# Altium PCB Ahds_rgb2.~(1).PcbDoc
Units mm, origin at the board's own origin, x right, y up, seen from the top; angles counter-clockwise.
Board outline 55.52 x 97.28 mm, 2 copper layers (Top Layer, Bottom Layer); 73 components, 40 nets, 226 pads, 1 vias.
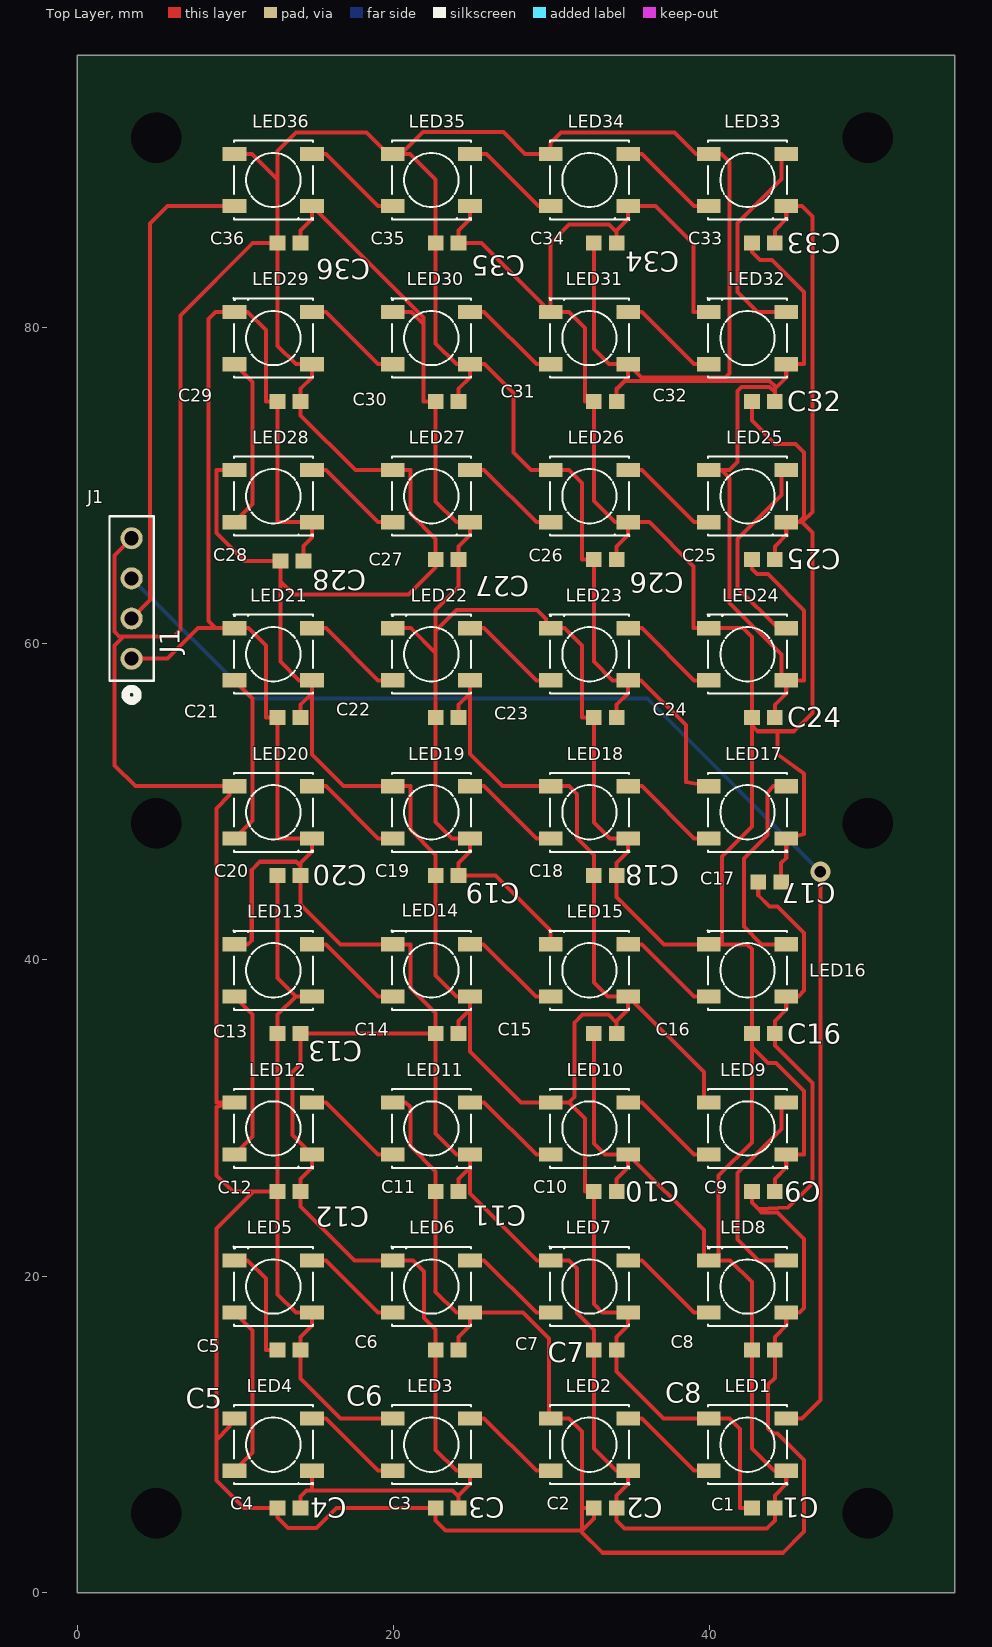
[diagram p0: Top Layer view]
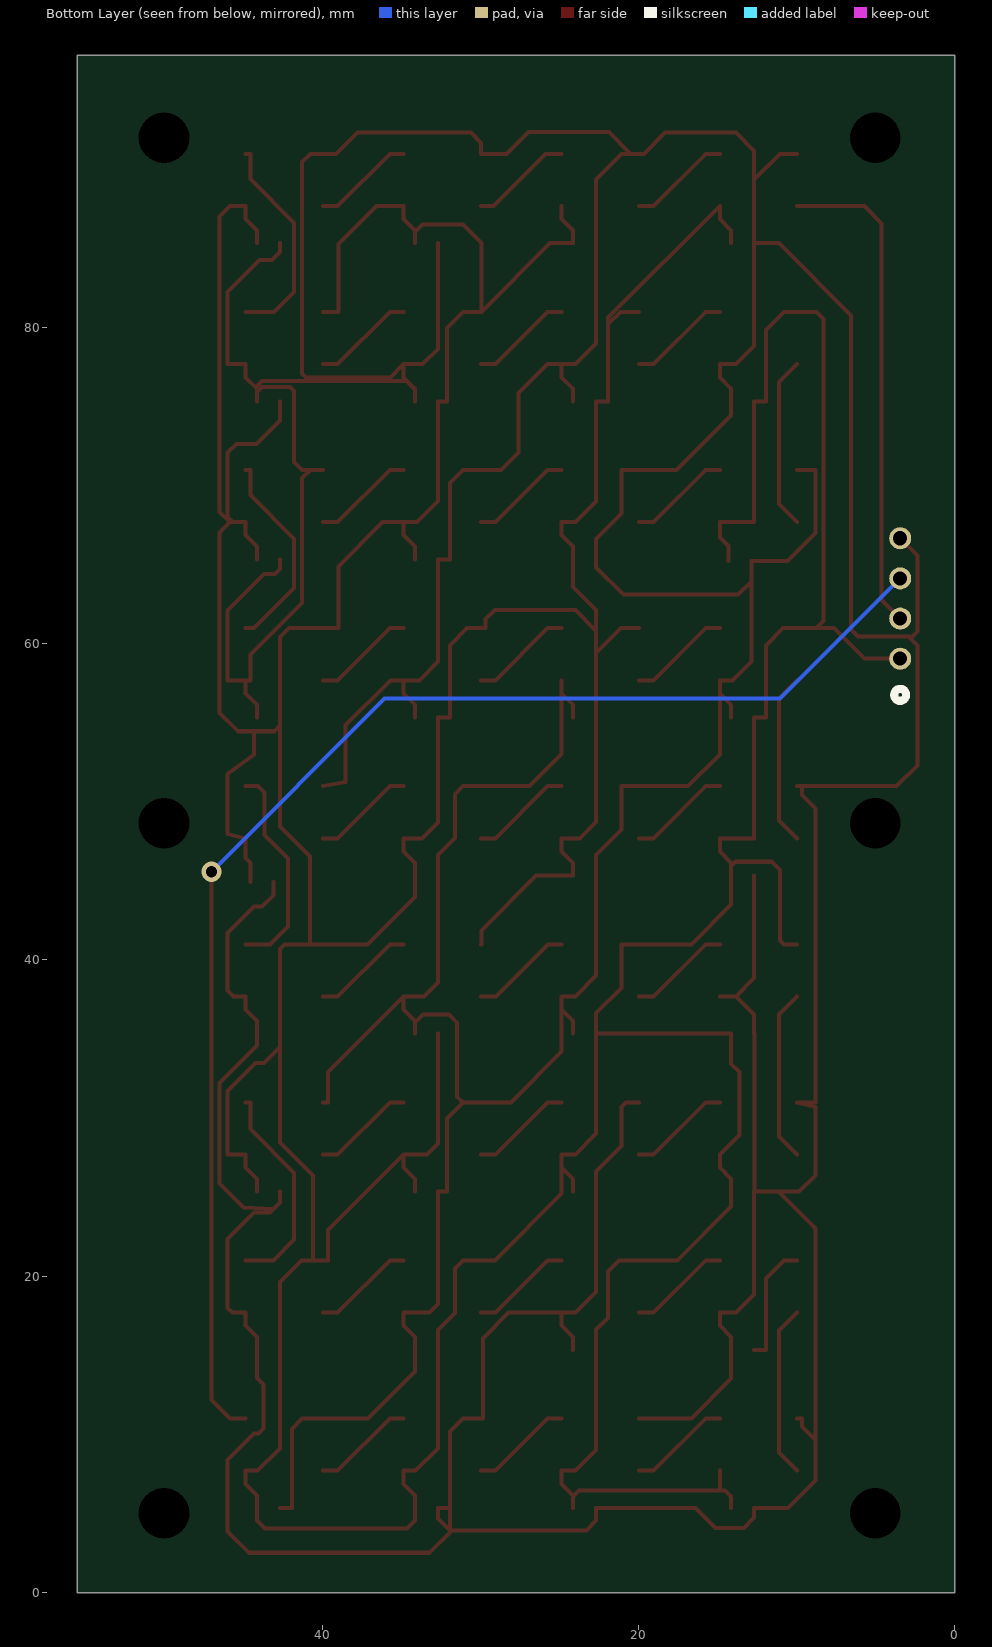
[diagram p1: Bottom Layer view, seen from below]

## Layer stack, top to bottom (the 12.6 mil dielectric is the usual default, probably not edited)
Top Solder: solder mask 0.0102, Solder Resist, Dk 3.5
Top Layer: signal copper 0.0356
Dielectric 1: dielectric 0.32, FR-4, Dk 4.8
Bottom Layer: signal copper 0.0356
Bottom Solder: solder mask 0.0102, Solder Resist, Dk 3.5

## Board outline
-0.018,-0.042 55.499,-0.042 55.499,97.24 -0.018,97.24

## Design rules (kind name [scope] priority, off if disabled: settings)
Clearance [All] p1: gap=0.254 ignorepadtopadclearanceinfootprint=TRUE
HoleSize [All] p1: absolutevalues=TRUE maxlimit=3.5 minlimit=0.025 maxpercent=80.000 minpercent=20.000
PolygonConnect [All] p1: connectstyle=Relief reliefconductorwidth=0.254 reliefentries=4 polygonreliefangle="90 Angle" airgapwidth=0.254
RoutingVias [All] p1: holewidth=0.711 width=1.27 viastyle="Through Hole" minholewidth=0.711 minwidth=1.27 maxholewidth=0.711 maxwidth=1.27
SolderMaskExpansion [All] p1: expansion=0.102 istentingtop=FALSE
Width [All] p1: maxlimit=0.254 minlimit=0.254 preferedwidth=0.254
29 further rules are at their usual default settings.

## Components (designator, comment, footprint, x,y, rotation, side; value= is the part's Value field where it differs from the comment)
C1 "100nF" CAPC17595_87N_KEM 43.393,5.339 r180 top
C2 "100nF" CAPC17595_87N_KEM 33.393,5.339 r180 top
C3 "100nF" CAPC17595_87N_KEM 23.393,5.339 r180 top
C4 "100nF" CAPC17595_87N_KEM 13.393,5.339 r180 top
C5 "100nF" CAPC17595_87N_KEM 13.393,15.339 r0 top
C6 "100nF" CAPC17595_87N_KEM 23.393,15.339 r0 top
C7 "100nF" CAPC17595_87N_KEM 33.393,15.339 r0 top
C8 "100nF" CAPC17595_87N_KEM 43.393,15.339 r0 top
C9 "100nF" CAPC17595_87N_KEM 43.393,25.339 r180 top
C10 "100nF" CAPC17595_87N_KEM 33.393,25.339 r180 top
C11 "100nF" CAPC17595_87N_KEM 23.393,25.339 r180 top
C12 "100nF" CAPC17595_87N_KEM 13.393,25.339 r180 top
C13 "100nF" CAPC17595_87N_KEM 13.393,35.339 r180 top
C14 "100nF" CAPC17595_87N_KEM 23.393,35.339 r0 top
C15 "100nF" CAPC17595_87N_KEM 33.393,35.339 r0 top
C16 "100nF" CAPC17595_87N_KEM 43.393,35.339 r0 top
C17 "100nF" CAPC17595_87N_KEM 43.797,44.916 r180 top
C18 "100nF" CAPC17595_87N_KEM 33.393,45.339 r180 top
C19 "100nF" CAPC17595_87N_KEM 23.393,45.339 r180 top
C20 "100nF" CAPC17595_87N_KEM 13.393,45.339 r180 top
C21 "100nF" CAPC17595_87N_KEM 13.393,55.339 r0 top
C22 "100nF" CAPC17595_87N_KEM 23.393,55.339 r0 top
C23 "100nF" CAPC17595_87N_KEM 33.393,55.339 r0 top
C24 "100nF" CAPC17595_87N_KEM 43.393,55.339 r0 top
C25 "100nF" CAPC17595_87N_KEM 43.393,65.339 r180 top
C26 "100nF" CAPC17595_87N_KEM 33.393,65.339 r180 top
C27 "100nF" CAPC17595_87N_KEM 23.393,65.339 r180 top
C28 "100nF" CAPC17595_87N_KEM 13.571,65.236 r180 top
C29 "100nF" CAPC17595_87N_KEM 13.393,75.339 r0 top
C30 "100nF" CAPC17595_87N_KEM 23.393,75.339 r0 top
C31 "100nF" CAPC17595_87N_KEM 33.393,75.339 r0 top
C32 "100nF" CAPC17595_87N_KEM 43.393,75.339 r0 top
C33 "100nF" CAPC17595_87N_KEM 43.393,85.339 r180 top
C34 "100nF" CAPC17595_87N_KEM 33.393,85.339 r180 top
C35 "100nF" CAPC17595_87N_KEM 23.393,85.339 r180 top
C36 "100nF" CAPC17595_87N_KEM 13.393,85.339 r180 top
J1 "901471304" CONN04_901471304_MOL 3.429,59.055 r90 top
LED1 "WS2812B" *WS2812B_WS2812B(Primary) 42.393,9.339 r0 top
LED2 "WS2812B" *WS2812B_WS2812B(Primary) 32.393,9.339 r0 top
LED3 "WS2812B" *WS2812B_WS2812B(Primary) 22.393,9.339 r0 top
LED4 "WS2812B" *WS2812B_WS2812B(Primary) 12.393,9.339 r0 top
LED5 "WS2812B" *WS2812B_WS2812B(Primary) 12.393,19.339 r180 top
LED6 "WS2812B" *WS2812B_WS2812B(Primary) 22.393,19.339 r180 top
LED7 "WS2812B" *WS2812B_WS2812B(Primary) 32.393,19.339 r180 top
LED8 "WS2812B" *WS2812B_WS2812B(Primary) 42.393,19.339 r180 top
LED9 "WS2812B" *WS2812B_WS2812B(Primary) 42.393,29.339 r0 top
LED10 "WS2812B" *WS2812B_WS2812B(Primary) 32.393,29.339 r0 top
LED11 "WS2812B" *WS2812B_WS2812B(Primary) 22.393,29.339 r0 top
LED12 "WS2812B" *WS2812B_WS2812B(Primary) 12.393,29.339 r0 top
LED13 "WS2812B" *WS2812B_WS2812B(Primary) 12.393,39.339 r180 top
LED14 "WS2812B" *WS2812B_WS2812B(Primary) 22.393,39.339 r180 top
LED15 "WS2812B" *WS2812B_WS2812B(Primary) 32.393,39.339 r180 top
LED16 "WS2812B" *WS2812B_WS2812B(Primary) 42.393,39.339 r180 top
LED17 "WS2812B" *WS2812B_WS2812B(Primary) 42.393,49.339 r0 top
LED18 "WS2812B" *WS2812B_WS2812B(Primary) 32.393,49.339 r0 top
LED19 "WS2812B" *WS2812B_WS2812B(Primary) 22.393,49.339 r0 top
LED20 "WS2812B" *WS2812B_WS2812B(Primary) 12.393,49.339 r0 top
LED21 "WS2812B" *WS2812B_WS2812B(Primary) 12.393,59.339 r180 top
LED22 "WS2812B" *WS2812B_WS2812B(Primary) 22.393,59.339 r180 top
LED23 "WS2812B" *WS2812B_WS2812B(Primary) 32.393,59.339 r180 top
LED24 "WS2812B" *WS2812B_WS2812B(Primary) 42.393,59.339 r180 top
LED25 "WS2812B" *WS2812B_WS2812B(Primary) 42.393,69.339 r0 top
LED26 "WS2812B" *WS2812B_WS2812B(Primary) 32.393,69.339 r0 top
LED27 "WS2812B" *WS2812B_WS2812B(Primary) 22.393,69.339 r0 top
LED28 "WS2812B" *WS2812B_WS2812B(Primary) 12.393,69.339 r0 top
LED29 "WS2812B" *WS2812B_WS2812B(Primary) 12.393,79.339 r180 top
LED30 "WS2812B" *WS2812B_WS2812B(Primary) 22.393,79.339 r180 top
LED31 "WS2812B" *WS2812B_WS2812B(Primary) 32.393,79.339 r180 top
LED32 "WS2812B" *WS2812B_WS2812B(Primary) 42.393,79.339 r180 top
LED33 "WS2812B" *WS2812B_WS2812B(Primary) 42.393,89.339 r0 top
LED34 "WS2812B" *WS2812B_WS2812B(Primary) 32.393,89.339 r0 top
LED35 "WS2812B" *WS2812B_WS2812B(Primary) 22.393,89.339 r0 top
LED36 "WS2812B" *WS2812B_WS2812B(Primary) 12.393,89.339 r0 top

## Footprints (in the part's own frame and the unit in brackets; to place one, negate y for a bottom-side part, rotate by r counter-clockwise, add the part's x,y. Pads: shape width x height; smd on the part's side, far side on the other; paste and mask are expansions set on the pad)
*WS2812B_WS2812B(Primary) [mm]
  rect 1.5x0.9 smd: 1(2.45,-1.65) 2(2.45,1.65) 3(-2.45,1.65) 4(-2.45,-1.65)
  silkscreen extent -2.5,-2.52 2.52,2.5
CAPC17595_87N_KEM [mm]
  rect 1x0.95 smd paste+0 mask+0: 1(-0.725,0) 2(0.725,0)
  body extent -0.87,-0.48 0.87,0.48, height 0.87
CONN04_901471304_MOL [mil]
  round 55 hole 35 paste-99999 mask+0: 1(0,0) 2(100,0) 3(200,0) 4(300,0)
  silkscreen extent -105,-55 355,55

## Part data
C1 C2 C3 C4 C5 C6 C7 C8 C9 C10 C11 C12 C13 C14 C15 C16 C17 C18 C19 C20 C21 C22 C23 C24 C25 C26 C27 C28 C29 C30 C31 C32 C33 C34 C35 C36: library part C0603C103K4RECTU, "ESD SMD Comm X7R, Ceramic, 0.01 uF, 10%, 16 VDC, X7R, SMD, MLCC, Temperature Stable, Electro Static Discharge, Class II, 0603", Manufacturer_Name=Kemet
J1: "C-Grid III PCB Receptacle, 2.54mm Pitch, Single Row, Vertical, Shrouded, 4 Circuits, 0.76Âµm Gold (Au) Plating", Manufacturer_Name=Molex
LED1 LED2 LED3 LED4 LED5 LED6 LED7 LED8 LED9 LED10 LED11 LED12 LED13 LED14 LED15 LED16 LED17 LED18 LED19 LED20 LED21 LED22 LED23 LED24 LED25 LED26 LED27 LED28 LED29 LED30 LED31 LED32 LED33 LED34 LED35 LED36: "Intelligent control LED integrated light source", Package=None

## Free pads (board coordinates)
  round 1.524 hole 3.2: 1(5,5) 2(50,5) 3(50,48.64) 4(50,92) 5(5,92) 6(5,48.64)

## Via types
v1: diameter 1.27, hole 0.711, Top Layer to Bottom Layer, 1 vias

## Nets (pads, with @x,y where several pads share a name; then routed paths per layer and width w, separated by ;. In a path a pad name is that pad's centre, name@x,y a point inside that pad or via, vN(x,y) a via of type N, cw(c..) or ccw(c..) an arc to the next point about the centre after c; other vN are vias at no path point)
5V: C1.1 C2.1 C3.1 C4.1 C6.1 C7.1 C8.1 C9.1 C10.1 C11.1 C12.1 C13.1 C14.1 C15.1 C16.1 C17.1 C18.1 C19.1 C20.1 C21.1 C22.1 C23.1 C24.1 C25.1 C26.1 C27.1 C28.1 C29.1 C30.1 C31.1 C32.1 C33.1 C34.1 C35.1 C36.1 J1.1 LED1.1 LED2.1 LED3.1 LED4.1 LED6.1 LED7.1 LED8.1 LED9.1 LED10.1 LED11.1 LED12.1 LED13.1 LED14.1 LED15.1 LED16.1 LED17.1 LED18.1 LED19.1 LED20.1 LED21.1 LED22.1 LED23.1 LED24.1 LED25.1 LED26.1 LED27.1 LED28.1 LED29.1 LED30.1 LED31.1 LED32.1 LED33.1 LED34.1 LED35.1 LED36.1 | length 535.7
  Top Layer w0.254: J1.1 5.697,59.055 7.631,60.989 8.725,60.989 ; LED13.1 10.777,40.989 11.031,41.243 11.031,45.678 11.565,46.212 13.839,46.212 14.118,45.932 ; C4.1@14.118,5.339 14.118,6.054 14.499,6.435 14.843,6.435 ; C36.1 14.118,86.14 14.843,86.865 LED36.1 21.902,80.63 21.902,80.222 ; C28.1 14.296,66.176 14.843,66.723 LED28.1 12.708,67.689 12.668,67.729 C29.1 11.92,75.339 11.92,79.846 10.777,80.989 LED29.1 8.725,80.989 8.288,80.552 8.288,61.426 8.725,60.989 ; LED4.1 14.843,6.435 ; LED22.1 21.09,60.989 22.668,59.411 ; LED30.1 21.135,80.989 21.902,80.222 ; C3.1@24.118,5.339 24.118,6.054 ; C11.1 24.118,26.146 24.843,26.871 ; LED35.1 24.843,86.865 24.118,86.14 C35.1 25.579,85.339 LED31.1@29.929,80.989 ; LED15.1 29.929,40.989 29.929,41.868 26.458,45.339 C19.1 24.118,46.135 24.843,46.86 LED19.1 23.701,47.689 22.668,48.722 22.668,55.339 22.668,59.411 ; C15.1@32.668,35.339 32.668,28.385 33.364,27.689 LED10.1 ; C10.1 34.118,26.146 34.843,26.871 LED10.1 ; C26.1 34.118,66.151 34.843,66.876 LED26.1 ; C34.1 34.118,86.04 ; LED32.1 38.971,80.989 38.971,85.277 36.559,87.689 LED34.1 34.843,86.865 34.118,86.14 34.118,86.04 ; C32.1 42.668,74.126 44.141,72.653 45.423,72.653 45.982,72.094 45.982,68.03 45.641,67.689 ; C9.1 44.118,26.146 44.843,26.871 LED9.1 45.982,27.689 45.982,31.708 44.204,33.486 43.684,33.486 42.668,34.502 ; C25.1 44.118,66.151 44.843,66.876 LED25.1 45.641,67.689 ; C33.1 44.118,86.14 44.843,86.865 LED33.1 45.829,87.689 46.49,87.029 46.49,68.35 45.829,67.689 ; C17.1 44.522,46.135 44.843,46.456 LED17.1 45.982,47.964 45.982,51.774 44.305,52.993 44.305,54.467 ; 8.725,60.989 LED21.1 10.833,60.989 11.92,59.902 11.92,55.339 C21.1 12.668,47.703 12.682,47.689 LED20.1 14.843,46.86 14.118,46.135 14.118,45.932 ; 14.118,45.932 C20.1 14.118,43.516 16.645,40.989 LED14.1 21.064,40.989 21.064,38.24 22.668,36.636 C14.1@22.668,35.339 ; 14.843,6.435 23.737,6.435 24.118,6.054 ; 21.902,80.222 21.902,75.339 22.668,75.339 22.668,69.006 23.985,67.689 LED27.1 24.843,66.876 24.118,66.151 C27.1 24.118,63.587 22.668,62.137 22.668,60.82 ; C14.1@22.668,35.339 22.668,29.006 23.985,27.689 LED11.1 24.843,26.871 ; C14.1@22.668,35.339 C13.1 14.118,33.424 13.597,32.902 13.597,28.936 LED12.1 14.843,26.871 14.118,26.146 C12.1 14.118,24.405 17.534,20.989 LED6.1 21.217,20.989 21.928,20.278 21.928,17.361 22.668,16.621 22.668,15.339 22.668,9.006 23.985,7.689 LED3.1 24.843,6.855 24.118,6.13 24.118,6.054 ; 22.668,59.411 22.668,60.82 ; 22.668,60.82 23.985,62.137 29.065,62.137 29.649,61.553 29.649,60.989 LED23.1 30.823,60.989 31.91,59.902 31.91,55.339 32.668,55.339 32.668,48.705 33.684,47.689 LED18.1 34.843,46.86 34.118,46.135 C18.1 34.118,43.988 37.117,40.989 LED16.1 40.775,40.989 ; 24.843,26.871 24.843,25.211 29.065,20.989 LED7.1 31.097,20.989 31.605,20.481 31.605,17.658 32.668,16.595 32.668,15.339 32.668,9.102 34.081,7.689 LED2.1 34.843,6.855 34.118,6.13 34.118,5.339 34.118,4.53 34.626,4.022 43.61,4.022 44.118,4.53 44.118,5.339 44.118,6.13 44.843,6.855 LED1.1 44.081,7.689 42.668,9.102 C8.1 42.668,19.618 41.297,20.989 LED8.1@40.571,20.989 ; LED31.1@29.929,80.989 29.929,85.353 31.097,86.521 33.637,86.521 34.118,86.04 ; LED31.1@29.929,80.989 LED31.1 31.097,80.989 32.113,79.973 32.113,75.339 32.668,75.339 32.668,69.025 34.004,67.689 LED26.1 ; LED10.1 39.632,22.901 39.632,20.989 LED8.1 LED8.1@40.571,20.989 ; LED26.1 36.177,67.689 38.971,64.895 38.971,60.989 LED24.1 42.095,60.989 42.668,60.416 C24.1 42.668,54.822 ; LED8.1@40.571,20.989 40.571,26.349 42.668,28.446 42.668,34.502 ; 40.775,40.989 42.375,40.989 42.668,40.696 C16.1 42.668,34.502 ; 40.775,40.989 40.775,46.542 42.668,48.435 42.668,54.822 ; 42.668,54.822 43.024,54.467 44.305,54.467 ; 44.305,54.467 45.321,54.467 46.49,55.635 46.49,67.029 45.829,67.689 ; 45.641,67.689 45.829,67.689
GND: C1.2 C2.2 C3.2 C4.2 C5.2 C6.2 C7.2 C8.2 C9.2 C10.2 C11.2 C12.2 C13.2 C14.2 C15.2 C16.2 C17.2 C18.2 C19.2 C20.2 C21.2 C22.2 C23.2 C24.2 C25.2 C26.2 C27.2 C28.2 C29.2 C30.2 C31.2 C32.2 C33.2 C34.2 C35.2 C36.2 J1.4 LED1.3 LED2.3 LED3.3 LED4.3 LED5.3 LED6.3 LED7.3 LED8.3 LED9.3 LED10.3 LED11.3 LED12.3 LED13.3 LED14.3 LED15.3 LED16.3 LED17.3 LED18.3 LED19.3 LED20.3 LED21.3 LED22.3 LED23.3 LED24.3 LED25.3 LED26.3 LED27.3 LED28.3 LED29.3 LED30.3 LED31.3 LED32.3 LED33.3 LED34.3 LED35.3 LED36.3 | length 662.7
  Top Layer w0.254: J1.4 2.344,65.59 2.344,60.766 2.649,60.461 2.903,60.461 ; LED4.3 9.634,10.989 9.634,10.474 8.796,9.636 ; LED20.3 LED20.3@9.634,50.989 ; LED28.3 8.796,70.989 8.796,67.014 10.574,65.236 C28.2 12.846,63.955 ; LED36.3 11.045,90.989 12.668,89.366 ; C20.2 12.668,38.846 13.825,37.689 ; C21.2 14.118,56.143 14.843,56.868 ; LED13.3 13.825,37.689 ; LED3.3 16.645,10.989 14.118,13.516 C5.2 14.118,16.138 14.843,16.863 LED5.3 13.825,17.689 12.668,18.846 C12.2 C12.2@12.657,25.339 ; LED11.3 20.767,30.989 21.064,30.692 21.064,28.232 22.668,26.628 22.668,25.339 22.668,19.006 23.985,17.689 LED6.3 ; C6.2 24.118,16.138 24.843,16.863 LED6.3 ; C14.2 24.118,36.128 24.843,36.864 ; C22.2 24.118,56.143 24.843,56.868 ; C30.2 24.118,76.133 24.843,76.858 LED30.3 ; LED22.3 24.843,56.868 ; C34.2@32.668,85.339 32.668,78.658 33.637,77.689 LED31.3 ; C15.2 34.118,36.026 ; C23.2 34.118,56.143 34.843,56.868 LED23.3 ; C31.2 34.118,76.08 ; LED9.3 39.632,30.989 39.632,32.901 LED15.3 ; LED17.3 38.512,51.266 38.512,54.847 35.669,57.689 LED23.3 ; LED25.3 40.749,70.989 ; C1.2@42.668,5.339 41.918,5.339 41.918,10.329 41.257,10.989 LED1.3 37.092,10.989 34.118,13.963 C7.2 34.118,16.138 34.843,16.863 LED7.3 33.204,17.689 32.668,18.225 32.668,25.339 32.113,25.339 32.113,29.973 31.097,30.989 ; C9.2 42.668,24.658 43.08,24.246 ; C25.2 42.668,64.728 42.987,64.409 43.684,64.409 45.982,62.112 45.982,57.689 LED24.3 ; C33.2 42.668,84.794 43.176,84.286 43.95,84.286 45.982,82.254 45.982,77.689 LED32.3 44.843,76.858 44.118,76.133 ; C17.2 43.072,44.092 43.797,43.367 44.305,43.367 45.982,41.69 45.982,38.058 45.613,37.689 LED16.3 44.843,36.853 44.118,36.128 C16.2 44.118,34.588 46.49,32.216 46.49,25.866 44.966,24.342 43.08,24.246 ; C24.2 44.118,56.143 44.843,56.868 LED24.3 ; C32.2 44.118,75.913 ; 2.903,60.461 6.104,60.461 6.535,60.893 6.535,80.781 11.094,85.339 C36.2 ; 2.903,60.461 2.344,59.902 2.344,52.31 3.665,50.989 LED20.3@9.634,50.989 ; 8.796,9.636 8.796,22.996 11.139,25.339 ; 8.796,9.636 8.796,7.07 10.527,5.339 12.668,5.339 12.668,4.722 13.317,4.073 15.121,4.073 16.387,5.339 22.668,5.339 22.668,4.53 23.278,3.921 31.91,3.921 ; LED20.3@9.634,50.989 9.634,50.428 8.796,49.59 8.796,30.989 LED12.3 8.796,30.692 8.796,26.374 9.831,25.339 11.139,25.339 ; 11.139,25.339 C12.2@12.657,25.339 ; C12.2@12.657,25.339 12.657,35.339 C13.2 12.668,36.534 13.825,37.689 ; C36.2 12.668,89.366 ; C36.2 12.668,78.846 13.825,77.689 LED29.3 14.843,76.858 14.118,76.133 C29.2 14.118,74.455 17.584,70.989 LED27.3 21.064,70.989 21.064,68.237 22.668,66.633 22.668,65.339 22.668,64.834 20.937,63.103 13.698,63.103 12.846,63.955 ; 12.668,89.366 12.668,91.181 13.825,92.338 18.293,92.338 19.642,90.989 LED35.3 LED35.3@20.477,90.989 ; 12.846,63.955 12.846,58.875 14.032,57.689 LED21.3 14.843,56.868 ; 14.843,56.868 14.843,52.994 16.848,50.989 LED19.3 21.064,50.989 21.064,48.247 22.668,46.643 22.668,45.339 22.668,39.006 23.985,37.689 LED14.3 24.843,36.864 ; LED35.3@20.477,90.989 21.045,90.989 22.668,89.366 22.668,85.339 22.668,79.006 23.985,77.689 LED30.3 ; LED35.3@20.477,90.989 21.852,92.363 26.954,92.363 28.329,90.989 LED34.3 29.943,91.692 30.589,92.338 37.775,92.338 39.124,90.989 LED33.3 40.749,90.989 41.257,90.481 41.257,77.098 41.003,76.844 35.688,76.844 LED31.3 ; LED6.3 28.202,17.689 29.827,16.064 29.827,10.989 LED2.3 31.097,10.989 31.91,10.176 31.91,5.339 ; 24.843,36.864 24.843,34.195 28.049,30.989 LED10.3 31.097,30.989 ; 24.843,56.868 24.843,53.027 26.881,50.989 LED18.3 31.097,50.989 31.605,50.481 31.605,47.706 32.668,46.643 32.668,45.339 32.668,38.582 33.561,37.689 LED15.3 ; LED30.3 25.756,77.689 27.579,75.866 27.579,72.094 28.684,70.989 LED26.3 31.097,70.989 31.91,70.176 31.91,65.339 32.668,65.339 32.668,58.865 33.844,57.689 LED23.3 ; 31.097,30.989 31.453,31.345 31.453,36.026 31.961,36.534 33.61,36.534 34.118,36.026 ; 31.91,3.921 31.91,5.339 ; 31.91,3.921 31.91,3.794 33.205,2.498 44.635,2.498 45.982,3.844 45.982,8.366 44.305,10.042 44.026,10.042 43.696,10.372 43.696,13.141 44.118,13.563 C8.2 44.118,16.138 44.843,16.863 LED8.3 45.679,17.689 45.982,17.992 45.982,22.361 44.305,24.037 43.289,24.037 43.08,24.246 ; 31.91,3.921 32.668,4.679 32.668,5.339 31.91,5.339 ; 34.118,36.026 34.118,36.128 34.843,36.853 LED15.3 ; 34.118,76.08 34.118,76.133 34.843,76.858 LED31.3 ; 34.118,76.08 34.653,76.615 43.797,76.615 44.118,76.294 44.118,76.133 ; 40.749,70.989 41.257,70.989 41.765,71.497 41.765,75.98 42.019,76.234 43.797,76.234 44.118,75.913 ; 40.749,70.989 41.257,70.481 41.257,62.595 44.534,59.318 44.534,57.689 LED24.3 ; 44.118,75.913 44.118,76.133
NetC5_1: C5.1 LED5.1 | length 7.7
  Top Layer w0.254: LED5.1 10.777,20.989 11.92,19.846 11.92,15.339 C5.1
NetJ1_2: J1.2 LED36.4 | length 31.3
  Top Layer w0.254: J1.2 4.605,62.771 4.605,86.597 5.697,87.689 LED36.4
NetJ1_3: J1.3 LED1.2 | length 87.3
  Top Layer w0.254: LED1.2 45.837,10.989 46.998,12.15 v1(46.998,45.577)
  Bottom Layer w0.254: J1.3 11.04,56.524 36.05,56.524 v1(46.998,45.577)
NetLED1_4: LED1.4 LED2.2 | length 6.5
  Top Layer w0.254: LED2.2 35.72,10.989 39.02,7.689 LED1.4
NetLED2_4: LED2.4 LED3.2 | length 6.5
  Top Layer w0.254: LED3.2 25.738,10.989 29.038,7.689 LED2.4
NetLED3_4: LED3.4 LED4.2 | length 6.5
  Top Layer w0.254: LED4.2 15.73,10.989 19.03,7.689 LED3.4
NetLED4_4: LED4.4 LED5.2 | length 10.9
  Top Layer w0.254: LED4.4 11.082,8.828 11.082,16.55 LED5.2
NetLED5_4: LED5.4 LED6.2 | length 6.5
  Top Layer w0.254: LED5.4 15.73,20.989 19.03,17.689 LED6.2
NetLED6_4: LED6.4 LED7.2 | length 6.5
  Top Layer w0.254: LED6.4 25.738,20.989 29.038,17.689 LED7.2
NetLED7_4: LED7.4 LED8.2 | length 6.5
  Top Layer w0.254: LED7.4 35.72,20.989 39.02,17.689 LED8.2
NetLED8_4: LED8.4 LED9.2 | length 13.8
  Top Layer w0.254: LED8.4 43.086,20.989 41.765,22.31 41.765,26.527 44.534,29.295 44.534,30.989 LED9.2
NetLED9_4: LED9.4 LED10.2 | length 6.5
  Top Layer w0.254: LED10.2 35.72,30.989 39.02,27.689 LED9.4
NetLED10_4: LED10.4 LED11.2 | length 6.5
  Top Layer w0.254: LED11.2 25.738,30.989 29.038,27.689 LED10.4
NetLED11_4: LED11.4 LED12.2 | length 6.5
  Top Layer w0.254: LED12.2 15.73,30.989 19.03,27.689 LED11.4
NetLED12_4: LED12.4 LED13.2 | length 10.9
  Top Layer w0.254: LED12.4 11.082,28.828 11.082,36.55 LED13.2
NetLED13_4: LED13.4 LED14.2 | length 6.5
  Top Layer w0.254: LED13.4 15.73,40.989 19.03,37.689 LED14.2
NetLED14_4: LED14.4 LED15.2 | length 6.5
  Top Layer w0.254: LED14.4 25.702,40.989 29.002,37.689 LED15.2
NetLED15_4: LED15.4 LED16.2 | length 6.5
  Top Layer w0.254: LED15.4 35.72,40.989 39.02,37.689 LED16.2
NetLED16_4: LED16.4 LED17.2 | length 13.6
  Top Layer w0.254: LED16.4 43.289,40.989 42.172,42.107 42.172,46.415 43.647,47.89 43.647,50.585 44.051,50.989 LED17.2
NetLED17_4: LED17.4 LED18.2 | length 6.5
  Top Layer w0.254: LED18.2 35.72,50.989 39.02,47.689 LED17.4
NetLED18_4: LED18.4 LED19.2 | length 6.5
  Top Layer w0.254: LED19.2 25.738,50.989 29.038,47.689 LED18.4
NetLED19_4: LED19.4 LED20.2 | length 6.5
  Top Layer w0.254: LED20.2 15.73,50.989 19.03,47.689 LED19.4
NetLED20_4: LED20.4 LED21.2 | length 10.9
  Top Layer w0.254: LED20.4 11.082,48.828 11.082,56.55 LED21.2
NetLED21_4: LED21.4 LED22.2 | length 6.5
  Top Layer w0.254: LED21.4 15.73,60.989 19.03,57.689 LED22.2
NetLED22_4: LED22.4 LED23.2 | length 6.5
  Top Layer w0.254: LED22.4 25.738,60.989 29.038,57.689 LED23.2
NetLED23_4: LED23.4 LED24.2 | length 6.5
  Top Layer w0.254: LED23.4 35.72,60.989 39.02,57.689 LED24.2
NetLED24_4: LED24.4 LED25.2 | length 13
  Top Layer w0.254: LED24.4 44.312,60.989 41.765,63.536 41.765,66.633 44.534,69.402 44.534,70.989 LED25.2
NetLED25_4: LED25.4 LED26.2 | length 6.5
  Top Layer w0.254: LED26.2 35.72,70.989 39.02,67.689 LED25.4
NetLED26_4: LED26.4 LED27.2 | length 6.5
  Top Layer w0.254: LED27.2 25.738,70.989 29.038,67.689 LED26.4
NetLED27_4: LED27.4 LED28.2 | length 6.5
  Top Layer w0.254: LED28.2 15.73,70.989 19.03,67.689 LED27.4
NetLED28_4: LED28.4 LED29.2 | length 10.9
  Top Layer w0.254: LED28.4 11.082,68.828 11.082,76.55 LED29.2
NetLED29_4: LED29.4 LED30.2 | length 6.5
  Top Layer w0.254: LED29.4 15.73,80.989 19.03,77.689 LED30.2
NetLED30_4: LED30.4 LED31.2 | length 6.5
  Top Layer w0.254: LED30.4 25.738,80.989 29.038,77.689 LED31.2
NetLED31_4: LED31.4 LED32.2 | length 6.5
  Top Layer w0.254: LED31.4 35.72,80.989 39.02,77.689 LED32.2
NetLED32_4: LED32.4 LED33.2 | length 13.8
  Top Layer w0.254: LED32.4 43.03,80.989 41.765,82.254 41.765,86.623 44.534,89.392 44.534,90.989 LED33.2
NetLED33_4: LED33.4 LED34.2 | length 6.5
  Top Layer w0.254: LED34.2 35.72,90.989 39.02,87.689 LED33.4
NetLED34_4: LED34.4 LED35.2 | length 6.5
  Top Layer w0.254: LED35.2 25.867,90.989 29.167,87.689 LED34.4
NetLED35_4: LED35.4 LED36.2 | length 6.5
  Top Layer w0.254: LED36.2 15.73,90.989 19.03,87.689 LED35.4

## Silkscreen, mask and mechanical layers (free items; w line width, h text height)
Mechanical 1:
  circle w0.254: c50,92 r3.5
  circle w0.254: c5,92 r3.5
  circle w0.254: c5,48.64 r3.5
  circle w0.254: c50,48.64 r3.5
  circle w0.254: c50,5 r3.5
  circle w0.254: c5,5 r3.5

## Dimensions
-0.018,-0.042 to -0.018,97.24 on Mechanical 1
-0.018,97.24 to 55.499,97.24 on Mechanical 1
